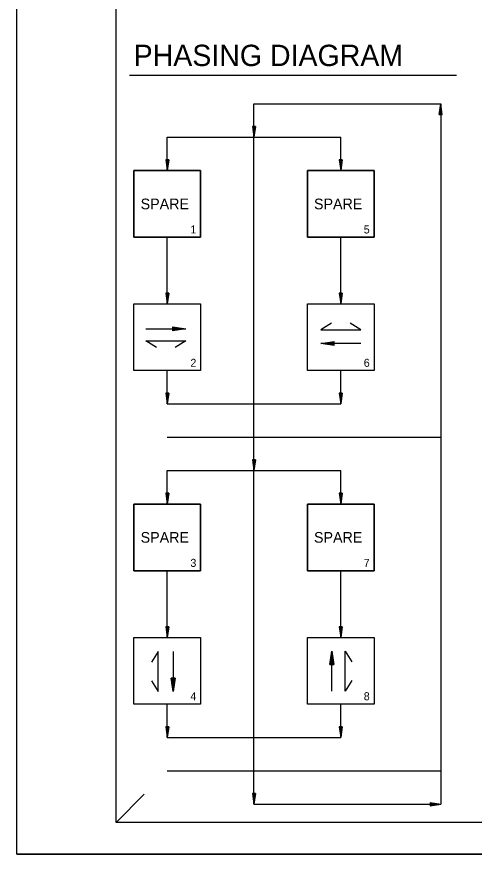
# Model space of a CAD drawing. Extents: x 1845362 to 1846362, y 750211 to 750851.
# Drawn here: x 1845361.6 to 1845533.2, y 750210.9 to 750524.9 of the extents above; entities that cross this region are included whole.
import ezdxf

# ---------------------------------------------------------------- set-up
doc = ezdxf.new("R2010")
doc.units = 0
for name, color, linetype in [('R_Border', 7, 'Continuous'), ('R_Draft', 7, 'Continuous'), ('R_Grid', 7, 'Continuous'), ('R_No Plot', 7, 'Continuous'), ('T_Drafting', 7, 'Continuous'), ('T_Notes', 7, 'Continuous')]:
    doc.layers.add(name, color=color, linetype=linetype)

msp = doc.modelspace()

# ---------------------------------------------------------------- linework, layer by layer
at = {"layer": 'R_Border'}
for p, q in [((1845398.86, 750222.89), (1845398.86, 750839.27)), ((1845398.86, 750222.89), (1845398.86, 750222.89)), ((1846347.4, 750222.89), (1845398.86, 750222.89))]:
    msp.add_line(p, q, dxfattribs=at)
at = {"layer": 'R_Draft'}
for p, q in [((1845519.99, 750488.25), (1845520.59, 750492.25)), ((1845520.09, 750488.25), (1845520.59, 750491.59)), ((1845521.19, 750488.25), (1845520.59, 750492.25)), ((1845521.09, 750488.25), (1845520.59, 750491.59)), ((1845520.19, 750488.25), (1845520.59, 750490.9)), ((1845520.29, 750488.25), (1845520.59, 750490.23)), ((1845520.39, 750488.25), (1845520.59, 750489.55)), ((1845520.49, 750488.25), (1845520.59, 750488.89)), ((1845520.98, 750488.25), (1845520.59, 750490.9)), ((1845520.88, 750488.25), (1845520.59, 750490.23)), ((1845520.78, 750488.25), (1845520.59, 750489.55)), ((1845520.68, 750488.25), (1845520.59, 750488.89)), ((1845519.99, 750488.25), (1845521.19, 750488.25)), ((1845449.99, 750483.75), (1845450.59, 750479.75)), ((1845451.19, 750483.75), (1845449.99, 750483.75)), ((1845450.09, 750483.75), (1845450.59, 750480.42)), ((1845450.19, 750483.75), (1845450.59, 750481.11)), ((1845450.29, 750483.75), (1845450.59, 750481.78)), ((1845450.39, 750483.75), (1845450.59, 750482.45)), ((1845450.49, 750483.75), (1845450.59, 750483.12)), ((1845451.19, 750483.75), (1845450.59, 750479.75)), ((1845450.78, 750483.75), (1845450.59, 750482.45)), ((1845450.98, 750483.75), (1845450.59, 750481.11)), ((1845451.09, 750483.75), (1845450.59, 750480.42)), ((1845450.88, 750483.75), (1845450.59, 750481.78)), ((1845450.68, 750483.75), (1845450.59, 750483.12)), ((1845417.49, 750471.25), (1845418.09, 750467.25)), ((1845418.69, 750471.25), (1845417.49, 750471.25)), ((1845417.59, 750471.25), (1845418.09, 750467.92)), ((1845417.69, 750471.25), (1845418.09, 750468.61)), ((1845417.79, 750471.25), (1845418.09, 750469.28)), ((1845417.89, 750471.25), (1845418.09, 750469.95)), ((1845417.99, 750471.25), (1845418.09, 750470.62)), ((1845418.69, 750471.25), (1845418.09, 750467.25)), ((1845418.28, 750471.25), (1845418.09, 750469.95)), ((1845418.48, 750471.25), (1845418.09, 750468.61)), ((1845418.59, 750471.25), (1845418.09, 750467.92)), ((1845418.38, 750471.25), (1845418.09, 750469.28)), ((1845418.18, 750471.25), (1845418.09, 750470.62)), ((1845482.49, 750471.25), (1845483.09, 750467.25)), ((1845483.69, 750471.25), (1845482.49, 750471.25)), ((1845482.59, 750471.25), (1845483.09, 750467.92)), ((1845482.69, 750471.25), (1845483.09, 750468.61)), ((1845482.79, 750471.25), (1845483.09, 750469.28)), ((1845482.89, 750471.25), (1845483.09, 750469.95)), ((1845482.99, 750471.25), (1845483.09, 750470.62)), ((1845483.69, 750471.25), (1845483.09, 750467.25)), ((1845483.28, 750471.25), (1845483.09, 750469.95)), ((1845483.48, 750471.25), (1845483.09, 750468.61)), ((1845483.59, 750471.25), (1845483.09, 750467.92)), ((1845483.38, 750471.25), (1845483.09, 750469.28)), ((1845483.18, 750471.25), (1845483.09, 750470.62)), ((1845417.49, 750421.25), (1845418.09, 750417.25)), ((1845418.69, 750421.25), (1845417.49, 750421.25)), ((1845417.59, 750421.25), (1845418.09, 750417.92)), ((1845417.69, 750421.25), (1845418.09, 750418.61)), ((1845417.79, 750421.25), (1845418.09, 750419.28)), ((1845417.89, 750421.25), (1845418.09, 750419.95)), ((1845417.99, 750421.25), (1845418.09, 750420.62)), ((1845418.69, 750421.25), (1845418.09, 750417.25)), ((1845418.28, 750421.25), (1845418.09, 750419.95)), ((1845418.48, 750421.25), (1845418.09, 750418.61)), ((1845418.59, 750421.25), (1845418.09, 750417.92)), ((1845418.38, 750421.25), (1845418.09, 750419.28)), ((1845418.18, 750421.25), (1845418.09, 750420.62)), ((1845482.49, 750421.25), (1845483.09, 750417.25)), ((1845483.69, 750421.25), (1845482.49, 750421.25)), ((1845482.59, 750421.25), (1845483.09, 750417.92)), ((1845482.69, 750421.25), (1845483.09, 750418.61)), ((1845482.79, 750421.25), (1845483.09, 750419.28)), ((1845482.89, 750421.25), (1845483.09, 750419.95)), ((1845482.99, 750421.25), (1845483.09, 750420.62)), ((1845483.69, 750421.25), (1845483.09, 750417.25)), ((1845483.28, 750421.25), (1845483.09, 750419.95)), ((1845483.48, 750421.25), (1845483.09, 750418.61)), ((1845483.59, 750421.25), (1845483.09, 750417.92)), ((1845483.38, 750421.25), (1845483.09, 750419.28)), ((1845483.18, 750421.25), (1845483.09, 750420.62)), ((1845417.49, 750383.75), (1845418.09, 750379.75)), ((1845418.69, 750383.75), (1845417.49, 750383.75)), ((1845417.59, 750383.75), (1845418.09, 750380.42)), ((1845417.69, 750383.75), (1845418.09, 750381.11)), ((1845417.79, 750383.75), (1845418.09, 750381.78)), ((1845417.89, 750383.75), (1845418.09, 750382.45)), ((1845417.99, 750383.75), (1845418.09, 750383.12)), ((1845418.69, 750383.75), (1845418.09, 750379.75)), ((1845418.28, 750383.75), (1845418.09, 750382.45)), ((1845418.48, 750383.75), (1845418.09, 750381.11)), ((1845418.59, 750383.75), (1845418.09, 750380.42)), ((1845418.38, 750383.75), (1845418.09, 750381.78)), ((1845418.18, 750383.75), (1845418.09, 750383.12)), ((1845482.49, 750383.75), (1845483.09, 750379.75)), ((1845483.69, 750383.75), (1845482.49, 750383.75)), ((1845482.59, 750383.75), (1845483.09, 750380.42)), ((1845482.69, 750383.75), (1845483.09, 750381.11)), ((1845482.79, 750383.75), (1845483.09, 750381.78)), ((1845482.89, 750383.75), (1845483.09, 750382.45)), ((1845482.99, 750383.75), (1845483.09, 750383.12)), ((1845483.69, 750383.75), (1845483.09, 750379.75)), ((1845483.28, 750383.75), (1845483.09, 750382.45)), ((1845483.48, 750383.75), (1845483.09, 750381.11)), ((1845483.59, 750383.75), (1845483.09, 750380.42)), ((1845483.38, 750383.75), (1845483.09, 750381.78)), ((1845483.18, 750383.75), (1845483.09, 750383.12)), ((1845449.99, 750358.75), (1845450.59, 750354.75)), ((1845451.19, 750358.75), (1845449.99, 750358.75)), ((1845450.09, 750358.75), (1845450.59, 750355.42)), ((1845450.19, 750358.75), (1845450.59, 750356.11)), ((1845450.29, 750358.75), (1845450.59, 750356.78)), ((1845450.39, 750358.75), (1845450.59, 750357.45)), ((1845450.49, 750358.75), (1845450.59, 750358.12)), ((1845451.19, 750358.75), (1845450.59, 750354.75)), ((1845450.78, 750358.75), (1845450.59, 750357.45)), ((1845450.98, 750358.75), (1845450.59, 750356.11)), ((1845451.09, 750358.75), (1845450.59, 750355.42)), ((1845450.88, 750358.75), (1845450.59, 750356.78)), ((1845450.68, 750358.75), (1845450.59, 750358.12)), ((1845417.49, 750346.25), (1845418.09, 750342.25)), ((1845418.69, 750346.25), (1845417.49, 750346.25)), ((1845417.59, 750346.25), (1845418.09, 750342.92)), ((1845417.69, 750346.25), (1845418.09, 750343.61)), ((1845417.79, 750346.25), (1845418.09, 750344.28)), ((1845417.89, 750346.25), (1845418.09, 750344.95)), ((1845417.99, 750346.25), (1845418.09, 750345.62)), ((1845418.69, 750346.25), (1845418.09, 750342.25)), ((1845418.28, 750346.25), (1845418.09, 750344.95)), ((1845418.48, 750346.25), (1845418.09, 750343.61)), ((1845418.59, 750346.25), (1845418.09, 750342.92)), ((1845418.38, 750346.25), (1845418.09, 750344.28)), ((1845418.18, 750346.25), (1845418.09, 750345.62)), ((1845482.49, 750346.25), (1845483.09, 750342.25)), ((1845483.69, 750346.25), (1845482.49, 750346.25)), ((1845482.59, 750346.25), (1845483.09, 750342.92)), ((1845482.69, 750346.25), (1845483.09, 750343.61)), ((1845482.79, 750346.25), (1845483.09, 750344.28)), ((1845482.89, 750346.25), (1845483.09, 750344.95)), ((1845482.99, 750346.25), (1845483.09, 750345.62)), ((1845483.69, 750346.25), (1845483.09, 750342.25)), ((1845483.28, 750346.25), (1845483.09, 750344.95)), ((1845483.48, 750346.25), (1845483.09, 750343.61)), ((1845483.59, 750346.25), (1845483.09, 750342.92)), ((1845483.38, 750346.25), (1845483.09, 750344.28)), ((1845483.18, 750346.25), (1845483.09, 750345.62)), ((1845417.49, 750296.25), (1845418.09, 750292.25)), ((1845418.69, 750296.25), (1845417.49, 750296.25)), ((1845417.59, 750296.25), (1845418.09, 750292.92)), ((1845417.69, 750296.25), (1845418.09, 750293.61)), ((1845417.79, 750296.25), (1845418.09, 750294.28)), ((1845417.89, 750296.25), (1845418.09, 750294.95)), ((1845417.99, 750296.25), (1845418.09, 750295.62)), ((1845418.69, 750296.25), (1845418.09, 750292.25)), ((1845418.28, 750296.25), (1845418.09, 750294.95)), ((1845418.48, 750296.25), (1845418.09, 750293.61)), ((1845418.59, 750296.25), (1845418.09, 750292.92)), ((1845418.38, 750296.25), (1845418.09, 750294.28)), ((1845418.18, 750296.25), (1845418.09, 750295.62)), ((1845482.49, 750296.25), (1845483.09, 750292.25)), ((1845483.69, 750296.25), (1845482.49, 750296.25)), ((1845482.59, 750296.25), (1845483.09, 750292.92)), ((1845482.69, 750296.25), (1845483.09, 750293.61)), ((1845482.79, 750296.25), (1845483.09, 750294.28)), ((1845482.89, 750296.25), (1845483.09, 750294.95)), ((1845482.99, 750296.25), (1845483.09, 750295.62)), ((1845483.69, 750296.25), (1845483.09, 750292.25)), ((1845483.28, 750296.25), (1845483.09, 750294.95)), ((1845483.48, 750296.25), (1845483.09, 750293.61)), ((1845483.59, 750296.25), (1845483.09, 750292.92)), ((1845483.38, 750296.25), (1845483.09, 750294.28)), ((1845483.18, 750296.25), (1845483.09, 750295.62)), ((1845417.49, 750258.75), (1845418.09, 750254.75)), ((1845418.69, 750258.75), (1845417.49, 750258.75)), ((1845417.59, 750258.75), (1845418.09, 750255.42)), ((1845417.69, 750258.75), (1845418.09, 750256.11)), ((1845417.79, 750258.75), (1845418.09, 750256.78)), ((1845417.89, 750258.75), (1845418.09, 750257.45)), ((1845417.99, 750258.75), (1845418.09, 750258.12)), ((1845418.69, 750258.75), (1845418.09, 750254.75)), ((1845418.28, 750258.75), (1845418.09, 750257.45)), ((1845418.48, 750258.75), (1845418.09, 750256.11)), ((1845418.59, 750258.75), (1845418.09, 750255.42)), ((1845418.38, 750258.75), (1845418.09, 750256.78)), ((1845418.18, 750258.75), (1845418.09, 750258.12)), ((1845482.49, 750258.75), (1845483.09, 750254.75)), ((1845483.69, 750258.75), (1845482.49, 750258.75)), ((1845482.59, 750258.75), (1845483.09, 750255.42)), ((1845482.69, 750258.75), (1845483.09, 750256.11)), ((1845482.79, 750258.75), (1845483.09, 750256.78)), ((1845482.89, 750258.75), (1845483.09, 750257.45)), ((1845482.99, 750258.75), (1845483.09, 750258.12)), ((1845483.69, 750258.75), (1845483.09, 750254.75)), ((1845483.28, 750258.75), (1845483.09, 750257.45)), ((1845483.48, 750258.75), (1845483.09, 750256.11)), ((1845483.59, 750258.75), (1845483.09, 750255.42)), ((1845483.38, 750258.75), (1845483.09, 750256.78)), ((1845483.18, 750258.75), (1845483.09, 750258.12)), ((1845449.99, 750233.75), (1845450.59, 750229.75)), ((1845451.19, 750233.75), (1845449.99, 750233.75)), ((1845450.09, 750233.75), (1845450.59, 750230.42)), ((1845450.19, 750233.75), (1845450.59, 750231.11)), ((1845450.29, 750233.75), (1845450.59, 750231.78)), ((1845450.39, 750233.75), (1845450.59, 750232.45)), ((1845450.49, 750233.75), (1845450.59, 750233.12)), ((1845451.19, 750233.75), (1845450.59, 750229.75)), ((1845450.78, 750233.75), (1845450.59, 750232.45)), ((1845450.98, 750233.75), (1845450.59, 750231.11)), ((1845451.09, 750233.75), (1845450.59, 750230.42)), ((1845450.88, 750233.75), (1845450.59, 750231.78)), ((1845450.68, 750233.75), (1845450.59, 750233.12)), ((1845516.59, 750230.35), (1845520.59, 750229.75)), ((1845516.59, 750230.35), (1845516.59, 750229.15)), ((1845516.59, 750230.25), (1845519.92, 750229.75)), ((1845516.59, 750230.15), (1845519.23, 750229.75)), ((1845516.59, 750230.05), (1845518.56, 750229.75)), ((1845516.59, 750229.95), (1845517.89, 750229.75)), ((1845516.59, 750229.85), (1845517.22, 750229.75)), ((1845516.59, 750229.15), (1845520.59, 750229.75)), ((1845516.59, 750229.56), (1845517.89, 750229.75)), ((1845516.59, 750229.36), (1845519.23, 750229.75)), ((1845516.59, 750229.25), (1845519.92, 750229.75)), ((1845516.59, 750229.46), (1845518.56, 750229.75)), ((1845516.59, 750229.66), (1845517.22, 750229.75))]:
    msp.add_line(p, q, dxfattribs=at)
at = {"layer": 'R_Grid'}
msp.add_line((1845398.86, 750222.89), (1845409.46, 750233.49), dxfattribs=at)
at = {"layer": 'R_No Plot'}
msp.add_line((1845361.65, 750210.95), (1846361.65, 750210.95), dxfattribs=at)
msp.add_lwpolyline([(1845361.63, 750850.95), (1846361.65, 750850.95), (1846361.65, 750210.94), (1845361.63, 750210.94)], close=True, dxfattribs=at)
at = {"layer": 'T_Drafting'}
for p, q in [((1845450.59, 750229.75), (1845450.59, 750492.25)), ((1845450.59, 750492.25), (1845520.59, 750492.25)), ((1845520.59, 750492.25), (1845520.59, 750229.75)), ((1845418.09, 750467.25), (1845418.09, 750479.75)), ((1845418.09, 750479.75), (1845483.09, 750479.75)), ((1845483.09, 750467.25), (1845483.09, 750479.75)), ((1845405.59, 750467.25), (1845405.59, 750442.25)), ((1845430.59, 750467.25), (1845405.59, 750467.25)), ((1845430.59, 750442.25), (1845430.59, 750467.25)), ((1845470.59, 750467.25), (1845470.59, 750442.25)), ((1845495.59, 750467.25), (1845470.59, 750467.25)), ((1845495.59, 750442.25), (1845495.59, 750467.25)), ((1845405.59, 750442.25), (1845430.59, 750442.25)), ((1845418.09, 750417.25), (1845418.09, 750442.25)), ((1845470.59, 750442.25), (1845495.59, 750442.25)), ((1845483.09, 750417.25), (1845483.09, 750442.25)), ((1845410.07, 750407.93), (1845425.07, 750407.93)), ((1845420.07, 750408.68), (1845425.07, 750407.93)), ((1845420.07, 750408.68), (1845420.07, 750407.18)), ((1845424.24, 750407.93), (1845420.07, 750408.56)), ((1845420.07, 750408.43), (1845423.38, 750407.93)), ((1845422.54, 750407.93), (1845420.07, 750408.31)), ((1845420.07, 750408.18), (1845421.7, 750407.93)), ((1845420.86, 750407.93), (1845420.07, 750408.05)), ((1845425.07, 750407.93), (1845420.07, 750407.18)), ((1845420.07, 750407.31), (1845424.24, 750407.93)), ((1845423.38, 750407.93), (1845420.07, 750407.44)), ((1845420.07, 750407.56), (1845422.54, 750407.93)), ((1845421.7, 750407.93), (1845420.07, 750407.69)), ((1845420.07, 750407.82), (1845420.86, 750407.93)), ((1845475.64, 750402.37), (1845480.64, 750403.12)), ((1845490.64, 750402.37), (1845475.64, 750402.37)), ((1845480.64, 750401.62), (1845475.64, 750402.37)), ((1845480.64, 750403), (1845476.48, 750402.37)), ((1845476.48, 750402.37), (1845480.64, 750401.75)), ((1845477.34, 750402.37), (1845480.64, 750402.87)), ((1845480.64, 750401.87), (1845477.34, 750402.37)), ((1845480.64, 750402.74), (1845478.17, 750402.37)), ((1845478.17, 750402.37), (1845480.64, 750402)), ((1845479.02, 750402.37), (1845480.64, 750402.62)), ((1845480.64, 750402.13), (1845479.02, 750402.37)), ((1845480.64, 750402.49), (1845479.85, 750402.37)), ((1845479.85, 750402.37), (1845480.64, 750402.25)), ((1845480.64, 750401.62), (1845480.64, 750403.12)), ((1845418.09, 750379.75), (1845418.09, 750392.25)), ((1845483.09, 750379.75), (1845483.09, 750392.25)), ((1845418.09, 750379.75), (1845483.09, 750379.75)), ((1845418.09, 750367.25), (1845520.59, 750367.25)), ((1845418.09, 750354.75), (1845483.09, 750354.75)), ((1845418.09, 750342.25), (1845418.09, 750354.75)), ((1845483.09, 750342.25), (1845483.09, 750354.75)), ((1845405.59, 750342.25), (1845405.59, 750317.25)), ((1845430.59, 750342.25), (1845405.59, 750342.25)), ((1845430.59, 750317.25), (1845430.59, 750342.25)), ((1845470.59, 750342.25), (1845470.59, 750317.25)), ((1845495.59, 750342.25), (1845470.59, 750342.25)), ((1845495.59, 750317.25), (1845495.59, 750342.25)), ((1845405.59, 750317.25), (1845430.59, 750317.25)), ((1845418.09, 750292.25), (1845418.09, 750317.25)), ((1845470.59, 750317.25), (1845495.59, 750317.25)), ((1845483.09, 750292.25), (1845483.09, 750317.25)), ((1845420.23, 750286.93), (1845420.23, 750271.93)), ((1845479.07, 750282.08), (1845479.82, 750287.08)), ((1845479.82, 750286.25), (1845479.19, 750282.08)), ((1845479.32, 750282.08), (1845479.82, 750285.39)), ((1845479.82, 750284.55), (1845479.44, 750282.08)), ((1845479.82, 750272.08), (1845479.82, 750287.08)), ((1845479.82, 750287.08), (1845480.57, 750282.08)), ((1845480.44, 750282.08), (1845479.82, 750286.25)), ((1845479.82, 750285.39), (1845480.31, 750282.08)), ((1845480.19, 750282.08), (1845479.82, 750284.55)), ((1845479.07, 750282.08), (1845480.57, 750282.08)), ((1845479.57, 750282.08), (1845479.82, 750283.71)), ((1845479.82, 750282.87), (1845479.7, 750282.08)), ((1845479.82, 750283.71), (1845480.06, 750282.08)), ((1845479.93, 750282.08), (1845479.82, 750282.87)), ((1845420.23, 750271.93), (1845419.48, 750276.93)), ((1845420.98, 750276.93), (1845419.48, 750276.93)), ((1845419.61, 750276.93), (1845420.23, 750272.77)), ((1845420.23, 750273.63), (1845419.73, 750276.93)), ((1845419.86, 750276.93), (1845420.23, 750274.46)), ((1845420.23, 750275.31), (1845419.99, 750276.93)), ((1845420.11, 750276.93), (1845420.23, 750276.14)), ((1845420.23, 750276.14), (1845420.35, 750276.93)), ((1845420.47, 750276.93), (1845420.23, 750275.31)), ((1845420.23, 750274.46), (1845420.6, 750276.93)), ((1845420.73, 750276.93), (1845420.23, 750273.63)), ((1845420.23, 750272.77), (1845420.86, 750276.93)), ((1845420.98, 750276.93), (1845420.23, 750271.93)), ((1845418.09, 750254.75), (1845418.09, 750267.25)), ((1845483.09, 750254.75), (1845483.09, 750267.25)), ((1845418.09, 750254.75), (1845483.09, 750254.75)), ((1845418.09, 750242.25), (1845520.59, 750242.25)), ((1845450.59, 750229.75), (1845520.59, 750229.75))]:
    msp.add_line(p, q, dxfattribs=at)
for points in [[(1845405.59, 750467.25), (1845430.59, 750467.25), (1845430.59, 750442.25), (1845405.59, 750442.25)], [(1845470.59, 750467.25), (1845495.59, 750467.25), (1845495.59, 750442.25), (1845470.59, 750442.25)], [(1845405.59, 750417.25), (1845430.59, 750417.25), (1845430.59, 750392.25), (1845405.59, 750392.25)], [(1845470.59, 750417.25), (1845495.59, 750417.25), (1845495.59, 750392.25), (1845470.59, 750392.25)], [(1845405.59, 750342.25), (1845430.59, 750342.25), (1845430.59, 750317.25), (1845405.59, 750317.25)], [(1845470.59, 750342.25), (1845495.59, 750342.25), (1845495.59, 750317.25), (1845470.59, 750317.25)], [(1845405.59, 750292.25), (1845430.59, 750292.25), (1845430.59, 750267.25), (1845405.59, 750267.25)], [(1845470.59, 750292.25), (1845495.59, 750292.25), (1845495.59, 750267.25), (1845470.59, 750267.25)]]:
    msp.add_lwpolyline(points, close=True, dxfattribs=at)
for points in [[(1845479.64, 750410), (1845475.64, 750407.5), (1845490.64, 750407.5), (1845486.64, 750410)], [(1845414.07, 750400.9), (1845410.07, 750403.4), (1845425.07, 750403.4), (1845421.07, 750400.9)], [(1845412.21, 750275.93), (1845414.71, 750271.93), (1845414.71, 750286.93), (1845412.21, 750282.93)], [(1845487.28, 750276.08), (1845484.78, 750272.08), (1845484.78, 750287.08), (1845487.28, 750283.08)]]:
    msp.add_lwpolyline(points, dxfattribs=at)
at = {"layer": 'T_Notes'}
msp.add_line((1845403.86, 750502.97), (1845526.51, 750502.97), dxfattribs=at)

# ---------------------------------------------------------------- texts
at = {"layer": 'T_Drafting'}
for p in [(1845408.09, 750452.75), (1845473.09, 750452.75), (1845408.09, 750327.75), (1845473.09, 750327.75)]:
    msp.add_text('SPARE', height=4, dxfattribs=at).set_placement(p)
at = {"layer": 'T_Notes'}
for s, height, p in [('PHASING DIAGRAM', 8, (1845405.46, 750506.44)), ('1', 3, (1845426.74, 750443.68)), ('5', 3, (1845491.74, 750443.68)), ('2', 3, (1845426.74, 750393.68)), ('6', 3, (1845491.74, 750393.68)), ('3', 3, (1845426.74, 750318.68)), ('7', 3, (1845491.74, 750318.68)), ('4', 3, (1845426.74, 750268.68)), ('8', 3, (1845491.74, 750268.68))]:
    msp.add_text(s, height=height, dxfattribs=at).set_placement(p)

doc.saveas('drawing.dxf')
